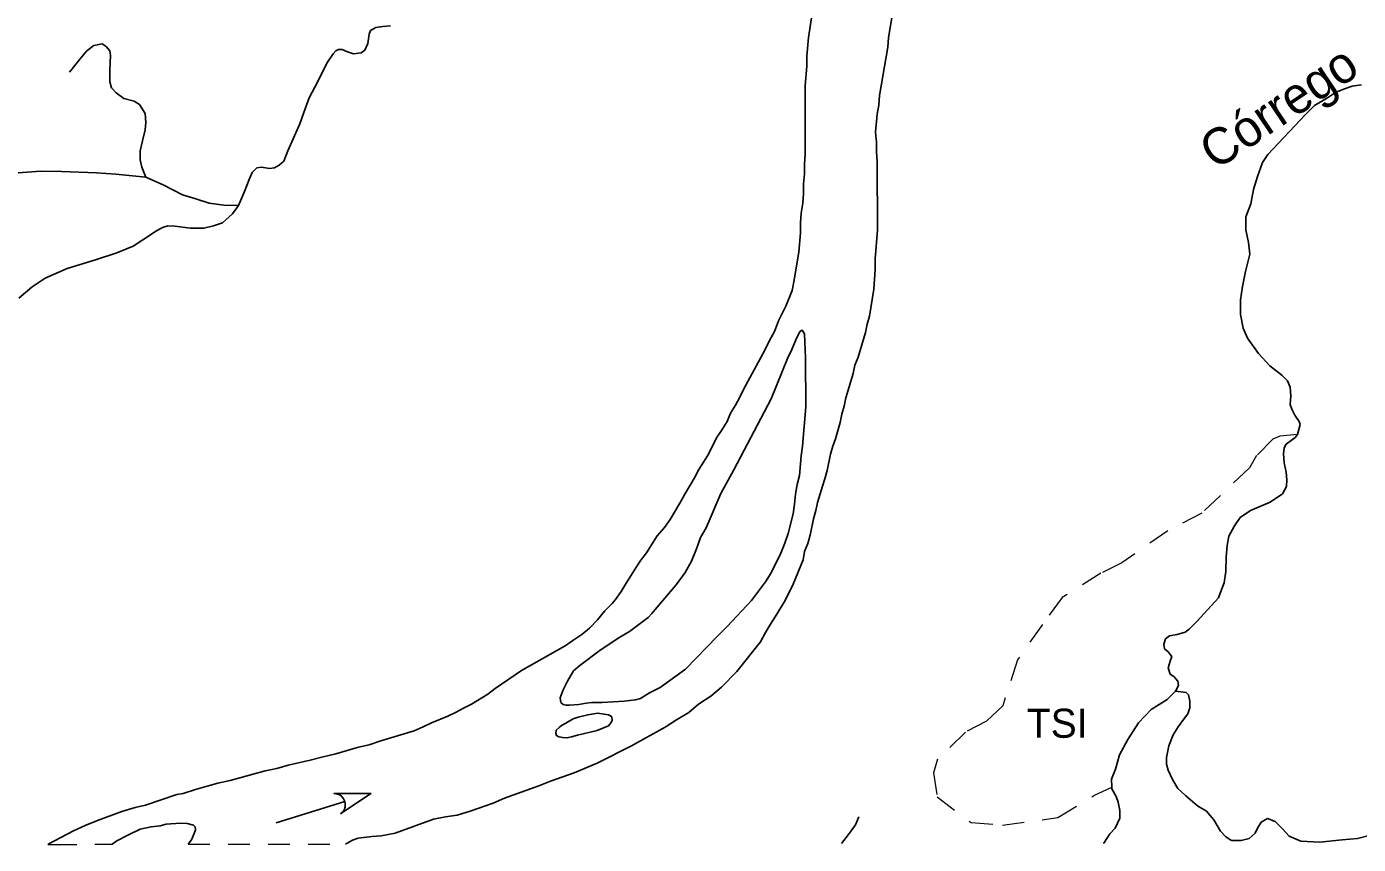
# Model space of a CAD drawing. Extents: x 436.3 to 500.4, y 8231 to 8286.4.
# Drawn here: x 478.01 to 485.33, y 8231.03 to 8235.53 of the extents above; entities that cross this region are included whole.
import ezdxf
from ezdxf.enums import TextEntityAlignment as Align

# ---------------------------------------------------------------- set-up
doc = ezdxf.new("R2010")
doc.units = 0
doc.header["$LTSCALE"] = 0.08
doc.linetypes.add('LONG_DASHED', pattern=[7.5, 6, -1.5])
doc.linetypes.add('SHORT_DASHED', pattern=[2.7, 1.5, -1.2])
for name, color, linetype, lineweight in [('10', 7, 'Continuous', 25), ('2', 7, 'Continuous', 25), ('21', 7, 'SHORT_DASHED', 13), ('62', 7, 'SHORT_DASHED', 13), ('9', 7, 'LONG_DASHED', 25)]:
    doc.layers.add(name, color=color, linetype=linetype, lineweight=lineweight)
doc.layers.add('61', color=7, linetype='Continuous')

msp = doc.modelspace()

# ---------------------------------------------------------------- linework, layer by layer
at = {"layer": '10'}
msp.add_line((479.3798, 8231.1504), (479.7583, 8231.2685), dxfattribs=at)
msp.add_lwpolyline([(479.7338, 8231.1999), (479.7463, 8231.2115), (479.7534, 8231.2209), (479.7599, 8231.2389), (479.7603, 8231.2615), (479.7583, 8231.2685), (479.7509, 8231.2836), (479.7411, 8231.2949), (479.7295, 8231.3043), (479.7155, 8231.3095), (479.6982, 8231.3118), (479.901, 8231.313)], close=True, dxfattribs=at)
at = {"layer": '2'}
for points in [[(478.1267, 8231.0327), (478.1276, 8231.0333), (478.2664, 8231.1076), (478.33, 8231.1366), (478.3975, 8231.1635), (478.5325, 8231.2128), (478.6045, 8231.2352), (478.663, 8231.2486), (478.834, 8231.3069), (478.87, 8231.3114), (478.9376, 8231.3338), (479.0006, 8231.3517), (479.0591, 8231.3696), (479.1266, 8231.383), (479.3202, 8231.4367), (479.3832, 8231.4501), (479.4462, 8231.468), (479.5678, 8231.4948), (479.6308, 8231.5127), (479.7073, 8231.5306), (479.8333, 8231.5664), (479.8918, 8231.5798), (479.9548, 8231.6022), (480.1381, 8231.6573), (480.1888, 8231.6783), (480.2338, 8231.7008), (480.3238, 8231.7366), (480.3688, 8231.759), (480.4092, 8231.7815), (480.4542, 8231.8039), (480.5441, 8231.8577), (480.5846, 8231.8891), (480.7284, 8231.9878), (480.9693, 8232.1231), (481.0116, 8232.1538), (481.0611, 8232.1852), (481.1015, 8232.2211), (481.1464, 8232.266), (481.1868, 8232.3154), (481.2272, 8232.3558), (481.2452, 8232.3782), (481.2765, 8232.4231), (481.3034, 8232.4681), (481.3303, 8232.5085), (481.3572, 8232.5534), (481.3841, 8232.5938), (481.4155, 8232.6342), (481.4738, 8232.7285), (481.5142, 8232.7734), (481.5456, 8232.8183), (481.5993, 8232.9081), (481.6262, 8232.9575), (481.68, 8233.0473), (481.7024, 8233.0922), (481.7293, 8233.1326), (481.7561, 8233.1775), (481.8009, 8233.2673), (481.8323, 8233.3122), (481.8592, 8233.3571), (481.8771, 8233.402), (481.9039, 8233.4469), (481.9263, 8233.4873), (481.9487, 8233.5322), (482.0655, 8233.7485), (482.0921, 8233.8016), (482.1189, 8233.851), (482.1413, 8233.9094), (482.1816, 8233.9902), (482.2168, 8234.077), (482.2263, 8234.1249), (482.2529, 8234.2866), (482.2617, 8234.3943), (482.2615, 8234.4482), (482.2659, 8234.5021), (482.2748, 8234.556), (482.2792, 8234.6099), (482.2791, 8234.6638), (482.2835, 8234.7177), (482.2834, 8234.7716), (482.2879, 8234.8254), (482.2874, 8235.2026), (482.2963, 8235.3103), (482.2963, 8235.3642), (482.3052, 8235.4675), (482.3232, 8235.5752)], [(479.7611, 8231.0342), (479.7991, 8231.0553), (479.8313, 8231.0667), (479.9052, 8231.0758), (479.9582, 8231.0804), (480.0342, 8231.0941), (480.2441, 8231.1703), (480.3117, 8231.1837), (480.3747, 8231.1926), (480.4467, 8231.215), (480.5727, 8231.2598), (480.6357, 8231.2867), (480.8247, 8231.3539), (480.8877, 8231.3808), (481.0182, 8231.4256), (481.1441, 8231.4794), (481.3331, 8231.5736), (481.5174, 8231.6768), (481.5804, 8231.7172), (481.6478, 8231.7575), (481.7017, 8231.8024), (481.7692, 8231.8473), (481.8276, 8231.8967), (481.9129, 8231.982), (482.0427, 8232.1451), (482.0699, 8232.1975), (482.0968, 8232.2425), (482.1237, 8232.2829), (482.1775, 8232.3727), (482.2222, 8232.4625), (482.2758, 8232.5973), (482.2847, 8232.6422), (482.3026, 8232.6871), (482.3159, 8232.732), (482.3337, 8232.8219), (482.347, 8232.8668), (482.3559, 8232.9117), (482.3826, 8233.0016), (482.396, 8233.042), (482.4094, 8233.0869), (482.4271, 8233.1768), (482.4405, 8233.2217), (482.4539, 8233.2621), (482.4806, 8233.3519), (482.4895, 8233.3969), (482.5028, 8233.4418), (482.5117, 8233.4867), (482.5518, 8233.6214), (482.5607, 8233.6663), (482.5786, 8233.7112), (482.6187, 8233.846), (482.6276, 8233.8909), (482.641, 8233.9358), (482.6647, 8234.084), (482.6718, 8234.1918), (482.6716, 8234.2502), (482.6847, 8234.4074), (482.6839, 8234.7846), (482.6793, 8234.8385), (482.6792, 8234.8924), (482.6746, 8234.9463), (482.6835, 8235.0451), (482.6924, 8235.0945), (482.6968, 8235.1483), (482.7416, 8235.4132), (482.746, 8235.4671), (482.764, 8235.5748)], [(478.4795, 8231.033), (478.5053, 8231.0514), (478.5683, 8231.0857), (478.6328, 8231.1155), (478.6927, 8231.1293), (478.7434, 8231.1338), (478.7757, 8231.143), (478.8542, 8231.1499), (478.891, 8231.1474), (478.9257, 8231.1382), (478.9349, 8231.129), (478.9373, 8231.1129), (478.9304, 8231.0922), (478.9144, 8231.0577), (478.896, 8231.0334)]]:
    msp.add_lwpolyline(points, dxfattribs=at)
for points in [[(481.4458, 8232.3022), (481.4256, 8232.2791), (481.3222, 8232.2029), (481.2683, 8232.1715), (481.1604, 8232.0997), (481.0484, 8232.0162), (481.0145, 8231.9862), (480.9808, 8231.9291), (480.9581, 8231.8827), (480.9412, 8231.8374), (480.9451, 8231.813), (480.9583, 8231.8017), (480.9715, 8231.7978), (480.9904, 8231.7978), (481.0434, 8231.8016), (481.0849, 8231.809), (481.1151, 8231.8128), (481.1717, 8231.8127), (481.2926, 8231.8202), (481.3549, 8231.8276), (481.3818, 8231.8342), (481.4313, 8231.8656), (481.4899, 8231.8952), (481.6291, 8231.9958), (481.8042, 8232.1754), (481.8591, 8232.23), (481.9928, 8232.3729), (482.069, 8232.4762), (482.1004, 8232.5256), (482.1541, 8232.6334), (482.1764, 8232.6873), (482.1943, 8232.7412), (482.221, 8232.849), (482.2298, 8232.9029), (482.2341, 8232.9568), (482.243, 8233.0107), (482.2563, 8233.0601), (482.265, 8233.168), (482.2738, 8233.2219), (482.2912, 8233.4375), (482.2904, 8233.7071), (482.2833, 8233.8393), (482.272, 8233.8582), (482.2585, 8233.8508), (482.2361, 8233.806), (482.2137, 8233.7521), (482.1914, 8233.7027), (482.1011, 8233.4819), (481.896, 8233.092), (481.8243, 8232.9618), (481.7438, 8232.7731), (481.7125, 8232.7192), (481.6901, 8232.6563), (481.6633, 8232.589), (481.6275, 8232.5261), (481.5781, 8232.4587), (481.4625, 8232.323)], [(481.0939, 8231.7447), (481.0399, 8231.7312), (481.0129, 8231.7223), (480.972, 8231.6996), (480.9492, 8231.6864), (480.9348, 8231.6756), (480.9193, 8231.6601), (480.9169, 8231.6433), (480.9217, 8231.6302), (480.9338, 8231.623), (480.9554, 8231.6194), (480.9782, 8231.6181), (481.0034, 8231.6229), (481.0356, 8231.6324), (481.1436, 8231.6592), (481.2063, 8231.6849), (481.2219, 8231.7029), (481.2267, 8231.7149), (481.2242, 8231.7328), (481.2182, 8231.74), (481.2065, 8231.7445), (481.1479, 8231.7536)]]:
    msp.add_lwpolyline(points, close=True, dxfattribs=at)
at = {"layer": '21'}
msp.add_lwpolyline([(484.9941, 8233.2856), (484.8966, 8233.2766), (484.8576, 8233.259), (484.7679, 8233.169), (484.7289, 8233.1025), (484.4675, 8232.8522), (484.2803, 8232.7563), (484.0287, 8232.5803), (483.9136, 8232.5235), (483.701, 8232.3886), (483.5918, 8232.2419), (483.4553, 8232.0464), (483.3734, 8231.794), (483.2837, 8231.7099), (483.1687, 8231.6493), (483.0146, 8231.5006), (482.9931, 8231.4263), (483.0126, 8231.2933), (483.1998, 8231.1525), (483.3715, 8231.1388), (483.6758, 8231.1799), (483.8748, 8231.3012), (483.9732, 8231.3466)], dxfattribs=at)
at = {"layer": '62'}
msp.add_line((478.896, 8231.0334), (479.7611, 8231.0342), dxfattribs=at)
msp.add_lwpolyline([(478.1267, 8231.0327), (478.164, 8231.0327), (478.4795, 8231.033)], dxfattribs=at)
at = {"layer": '9'}
for points in [[(479.1724, 8234.544), (479.2058, 8234.6203), (479.2312, 8234.6869), (479.2489, 8234.726), (479.2745, 8234.7514), (479.3, 8234.7553), (479.3433, 8234.7474), (479.3708, 8234.7512), (479.3963, 8234.7649), (479.4219, 8234.7883), (479.4435, 8234.845), (479.5103, 8234.9918), (479.5322, 8235.0559), (479.5616, 8235.1361), (479.6088, 8235.2261), (479.658, 8235.3258), (479.6933, 8235.3766), (479.709, 8235.3942), (479.7228, 8235.402), (479.7424, 8235.4019), (479.7719, 8235.3882), (479.8053, 8235.3783), (479.8466, 8235.3821), (479.8682, 8235.3977), (479.8839, 8235.4349), (479.8918, 8235.4858), (479.8996, 8235.5054), (479.9272, 8235.5229), (479.9665, 8235.5268), (480.0081, 8235.5314)], [(478.2449, 8235.2772), (478.3034, 8235.3507), (478.3404, 8235.3935), (478.3774, 8235.4241), (478.4236, 8235.4332), (478.4451, 8235.4178), (478.4666, 8235.3932), (478.4697, 8235.3686), (478.4666, 8235.2889), (478.4666, 8235.2244), (478.4759, 8235.1907), (478.5005, 8235.1629), (478.5436, 8235.1322), (478.5991, 8235.1166), (478.6299, 8235.0982), (478.6606, 8235.049), (478.6637, 8234.9999), (478.6607, 8234.96), (478.6453, 8234.8986), (478.633, 8234.8434), (478.633, 8234.7943), (478.6423, 8234.7545), (478.6639, 8234.6991)], [(484.9941, 8233.2856), (485.0081, 8233.3398), (485.0024, 8233.3568), (484.9795, 8233.3908), (484.9622, 8233.4248), (484.9536, 8233.4504), (484.9563, 8233.4986), (484.953, 8233.5458), (484.9387, 8233.5798), (484.9071, 8233.611), (484.8415, 8233.662), (484.7784, 8233.7301), (484.7183, 8233.8151), (484.6953, 8233.869), (484.6808, 8233.9455), (484.6805, 8234.0249), (484.6917, 8234.0985), (484.7085, 8234.1807), (484.7314, 8234.2757), (484.7241, 8234.3397), (484.7096, 8234.4109), (484.7093, 8234.4819), (484.7378, 8234.5531), (484.7519, 8234.6313), (484.7732, 8234.7024), (484.8017, 8234.7806), (484.8302, 8234.8233), (485.0374, 8235.0436), (485.0874, 8235.0934), (485.1589, 8235.1359), (485.2018, 8235.1644), (485.252, 8235.1857), (485.2949, 8235.1998), (485.345, 8235.207)], [(477.9362, 8234.7214), (478.0871, 8234.7333), (478.2011, 8234.73), (478.392, 8234.7234), (478.4998, 8234.7169), (478.6639, 8234.6991)], [(478.6639, 8234.6991), (478.7585, 8234.6579), (478.8662, 8234.6024), (478.9384, 8234.5808), (479.0122, 8234.556), (479.0924, 8234.5465), (479.1724, 8234.544)], [(477.9653, 8234.0349), (478.0388, 8234.0962), (478.1115, 8234.1451), (478.2314, 8234.1978), (478.3866, 8234.2445), (478.5046, 8234.2833), (478.5937, 8234.3211), (478.6468, 8234.3543), (478.7233, 8234.4051), (478.7548, 8234.4227), (478.7842, 8234.4324), (478.8236, 8234.4304), (478.9101, 8234.4184), (478.9828, 8234.4202), (479.036, 8234.4317), (479.0851, 8234.4493), (479.14, 8234.4982), (479.1724, 8234.544)], [(484.3228, 8231.8751), (484.3397, 8231.9063), (484.3368, 8231.929), (484.314, 8231.9544), (484.294, 8231.9686), (484.2824, 8232.0027), (484.2937, 8232.0395), (484.3022, 8232.065), (484.2821, 8232.0905), (484.2621, 8232.1075), (484.2592, 8232.1331), (484.2676, 8232.1614), (484.2903, 8232.1784), (484.3331, 8232.1869), (484.3758, 8232.1982), (484.3985, 8232.2152), (484.4383, 8232.2549), (484.5007, 8232.3229), (484.5603, 8232.388), (484.5744, 8232.4277), (484.5914, 8232.4702), (484.5997, 8232.5326), (484.6024, 8232.6103), (484.6078, 8232.6755), (484.6162, 8232.7265), (484.6474, 8232.7832), (484.6785, 8232.8285), (484.7354, 8232.8681), (484.8436, 8232.9135), (484.9118, 8232.9588), (484.9324, 8232.9997), (484.9351, 8233.0365), (484.9321, 8233.0791), (484.9205, 8233.1301), (484.9175, 8233.1783), (484.9202, 8233.2123), (484.9316, 8233.2321), (484.9657, 8233.2577), (484.9814, 8233.2697), (484.9941, 8233.2856)], [(484.3228, 8231.8751), (484.2773, 8231.8297), (484.1888, 8231.7741), (484.1206, 8231.7004), (484.0611, 8231.6097), (484.0158, 8231.5248), (483.9933, 8231.4454), (483.9707, 8231.3915), (483.9732, 8231.3466)], [(484.3228, 8231.8751), (484.3821, 8231.8673), (484.3942, 8231.8553), (484.4025, 8231.8191), (484.4026, 8231.7829), (484.3906, 8231.7507), (484.3664, 8231.7185), (484.3383, 8231.6782), (484.3101, 8231.634), (484.286, 8231.5736), (484.2741, 8231.5092), (484.2742, 8231.473), (484.2824, 8231.4408), (484.3068, 8231.3885), (484.3353, 8231.3402), (484.3799, 8231.2999), (484.4448, 8231.2436), (484.4934, 8231.2154), (484.534, 8231.167), (484.5709, 8231.1061), (484.5992, 8231.074), (484.6317, 8231.0538), (484.6842, 8231.0538), (484.7287, 8231.0658), (484.761, 8231.094), (484.7731, 8231.1221), (484.7932, 8231.1544), (484.8296, 8231.1744), (484.8701, 8231.1583), (484.9106, 8231.1181), (484.9471, 8231.0778), (485.012, 8231.0497), (485.1172, 8231.0455), (485.2385, 8231.0576), (485.3235, 8231.0657), (485.3881, 8231.0817)], [(483.9732, 8231.3466), (483.9737, 8231.3377), (483.9966, 8231.2951), (484.0081, 8231.2639), (484.0168, 8231.2186), (484.0169, 8231.1761), (483.9915, 8231.1222), (483.963, 8231.091), (483.929, 8231.04), (483.9267, 8231.0376)], [(482.583, 8231.1834), (482.5642, 8231.1402), (482.5263, 8231.0861), (482.4867, 8231.0366)]]:
    msp.add_lwpolyline(points, dxfattribs=at)

# ---------------------------------------------------------------- texts
at = {"layer": '61'}
msp.add_text('Córrego                                 Fino', height=0.2, rotation=33.776, dxfattribs=at).set_placement((486.18, 8235.8288), align=Align.CENTER)
msp.add_text('TSI', height=0.16, dxfattribs=at).set_placement((483.673, 8231.6185), align=Align.CENTER)

doc.saveas('drawing.dxf')
